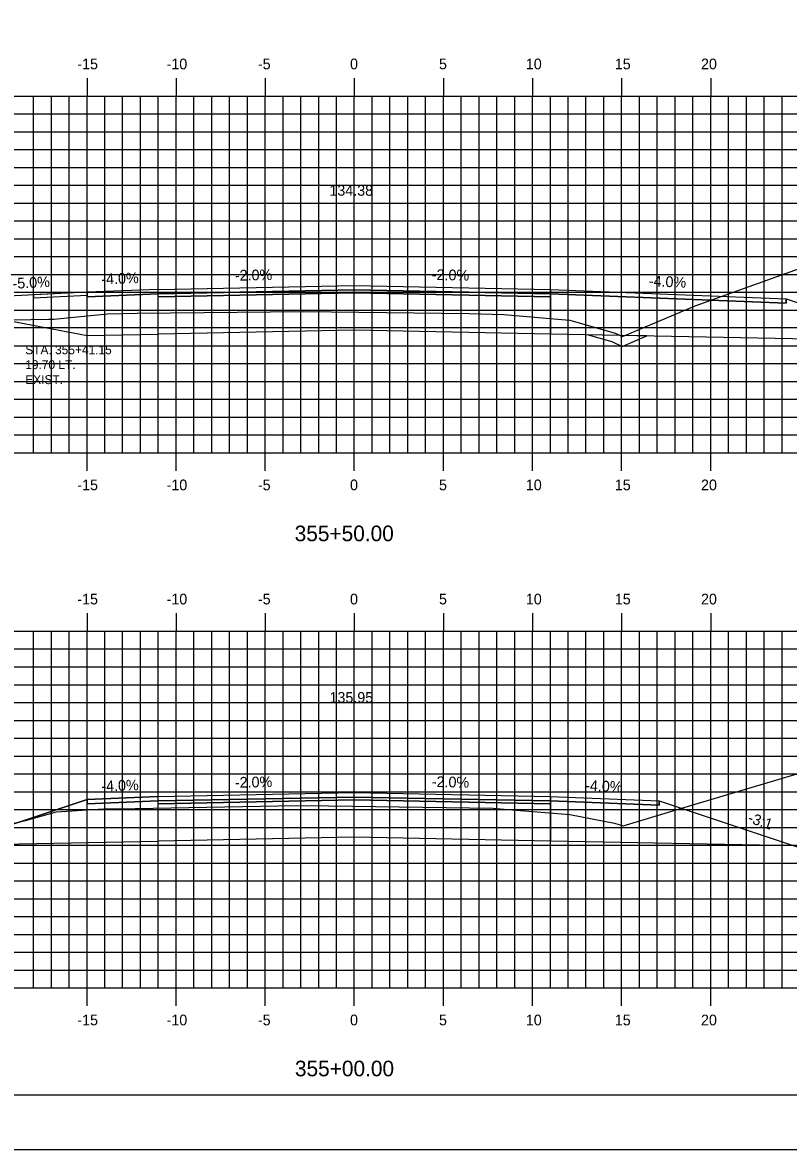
# Model space of a CAD drawing. Extents: x 1145416 to 1145586, y 608981 to 609091.
# Drawn here: x 1145480.3 to 1145523.3, y 608981.3 to 609044.5 of the extents above; entities that cross this region are included whole.
import ezdxf

# ---------------------------------------------------------------- set-up
doc = ezdxf.new("R2010")
doc.units = 0
for name, color, linetype in [('ANNOTATION', 7, 'Continuous'), ('BORDER', 7, 'Continuous'), ('D_Roadway_Centerline', 7, 'Continuous'), ('D_Roadway_Centerline_Text', 7, 'Continuous'), ('D_Roadway_Edge_Shoulder', 7, 'Continuous'), ('D_Roadway_Edge_TW', 7, 'Continuous'), ('D_Roadway_Pavement', 7, 'Continuous'), ('D_Roadway_SubGrade', 7, 'Continuous'), ('D_Text_Monospaced', 7, 'Continuous'), ('H_V ANNOTATION', 7, 'Continuous'), ('MAJOR', 7, 'Continuous'), ('MINOR', 7, 'Continuous'), ('PLOT BOUNDARY', 7, 'Continuous'), ('S_Roadway_Centerline', 7, 'Continuous'), ('SHADING', 7, 'Continuous')]:
    doc.layers.add(name, color=color, linetype=linetype)

msp = doc.modelspace()

# ---------------------------------------------------------------- linework, layer by layer
msp.add_lwpolyline([(1145459.897, 609002.864), (1145461.147, 609002.721), (1145462.397, 609002.44), (1145463.647, 609002.022), (1145464.897, 609001.465), (1145473.164, 608997.332), (1145476.164, 608998.332), (1145483.888, 609000.906), (1145483.889, 609000.906), (1145487.889, 609001.066), (1145498.889, 609001.286), (1145509.889, 609001.066), (1145515.987, 609000.823), (1145523.577, 608998.293), (1145526.577, 608997.293), (1145535.165, 609001.587), (1145536.415, 609002.14), (1145537.665, 609002.548), (1145538.915, 609002.812), (1145540.165, 609002.931)])
at = {"layer": 'BORDER'}
msp.add_lwpolyline([(1145423.889, 608984.335), (1145583.889, 608984.335), (1145583.889, 609089.335), (1145423.889, 609089.335)], close=True, dxfattribs=at)
at = {"layer": 'D_Roadway_Edge_Shoulder'}
for points in [[(1145483.889, 609029.335), (1145480.889, 609029.188), (1145480.889, 609029.021), (1145483.889, 609029.171)], [(1145487.889, 609029.495), (1145483.889, 609029.335), (1145483.889, 609029.085), (1145487.889, 609029.245)], [(1145509.889, 609029.495), (1145523.13, 609028.966), (1145523.13, 609028.716), (1145509.889, 609029.245)], [(1145487.889, 609001.066), (1145483.889, 609000.906), (1145483.889, 609000.656), (1145487.889, 609000.816)], [(1145509.889, 609001.066), (1145515.987, 609000.823), (1145515.987, 609000.573), (1145509.889, 609000.816)]]:
    msp.add_lwpolyline(points, close=True, dxfattribs=at)
at = {"layer": 'D_Roadway_Edge_TW'}
for points in [[(1145487.889, 609029.245), (1145487.889, 609029.495), (1145498.889, 609029.715), (1145509.889, 609029.495), (1145509.889, 609029.245), (1145498.889, 609029.465)], [(1145487.889, 609000.816), (1145487.889, 609001.066), (1145498.889, 609001.286), (1145509.889, 609001.066), (1145509.889, 609000.816), (1145498.889, 609001.036)]]:
    msp.add_lwpolyline(points, close=True, dxfattribs=at)
at = {"layer": 'D_Roadway_Pavement'}
for points in [[(1145487.889, 609029.079), (1145487.889, 609029.245), (1145498.889, 609029.465), (1145509.889, 609029.245), (1145509.889, 609029.079), (1145498.889, 609029.299)], [(1145487.889, 609000.65), (1145487.889, 609000.816), (1145498.889, 609001.036), (1145509.889, 609000.816), (1145509.889, 609000.65), (1145498.889, 609000.87)]]:
    msp.add_lwpolyline(points, close=True, dxfattribs=at)
at = {"layer": 'D_Roadway_SubGrade'}
for points in [[(1145477.987, 609028.04), (1145483.889, 609026.915), (1145487.889, 609026.995), (1145487.889, 609029.079), (1145487.889, 609029.245), (1145483.889, 609029.085), (1145483.889, 609029.335), (1145477.987, 609029.04)], [(1145487.889, 609026.995), (1145487.889, 609029.079), (1145498.889, 609029.299), (1145509.889, 609029.079), (1145509.889, 609026.995), (1145498.889, 609027.215)], [(1145509.889, 609029.079), (1145509.889, 609029.245), (1145523.13, 609028.716), (1145523.13, 609028.966), (1145523.13, 609028.966), (1145530.264, 609026.588), (1145509.889, 609026.995)], [(1145487.889, 609000.65), (1145487.889, 609000.816), (1145483.889, 609000.656), (1145483.889, 609000.906), (1145483.888, 609000.906), (1145476.164, 608998.332), (1145487.889, 608998.566)], [(1145487.889, 608998.566), (1145487.889, 609000.65), (1145498.889, 609000.87), (1145509.889, 609000.65), (1145509.889, 608998.566), (1145498.889, 608998.786)], [(1145509.889, 609000.65), (1145509.889, 609000.816), (1145515.987, 609000.573), (1145515.987, 609000.823), (1145515.987, 609000.823), (1145523.577, 608998.293), (1145509.889, 608998.566)]]:
    msp.add_lwpolyline(points, close=True, dxfattribs=at)
msp.add_lwpolyline([(1145512.02, 609026.953), (1145513.341, 609026.572), (1145513.92, 609026.299), (1145515.303, 609026.887)], dxfattribs=at)
at = {"layer": 'MAJOR'}
for p, q in [((1145483.889, 609041.337), (1145483.889, 609040.335)), ((1145488.889, 609041.337), (1145488.889, 609040.335)), ((1145493.889, 609041.337), (1145493.889, 609040.335)), ((1145498.889, 609041.337), (1145498.889, 609040.335)), ((1145503.889, 609041.337), (1145503.889, 609040.335)), ((1145508.889, 609041.337), (1145508.889, 609040.335)), ((1145513.889, 609041.337), (1145513.889, 609040.335)), ((1145518.889, 609041.337), (1145518.889, 609040.335)), ((1145428.889, 609040.335), (1145568.889, 609040.335)), ((1145428.889, 609040.335), (1145568.889, 609040.335)), ((1145483.889, 609020.335), (1145483.889, 609040.335)), ((1145488.889, 609020.335), (1145488.889, 609040.335)), ((1145493.889, 609020.335), (1145493.889, 609040.335)), ((1145498.889, 609020.335), (1145498.889, 609040.335)), ((1145503.889, 609020.335), (1145503.889, 609040.335)), ((1145508.889, 609020.335), (1145508.889, 609040.335)), ((1145513.889, 609020.335), (1145513.889, 609040.335)), ((1145518.889, 609020.335), (1145518.889, 609040.335)), ((1145428.889, 609035.335), (1145568.889, 609035.335)), ((1145428.889, 609030.335), (1145568.889, 609030.335)), ((1145428.889, 609025.335), (1145568.889, 609025.335)), ((1145428.889, 609020.335), (1145568.889, 609020.335)), ((1145428.889, 609020.335), (1145568.889, 609020.335)), ((1145483.889, 609019.333), (1145483.889, 609020.335)), ((1145488.889, 609019.333), (1145488.889, 609020.335)), ((1145493.889, 609019.333), (1145493.889, 609020.335)), ((1145498.889, 609019.333), (1145498.889, 609020.335)), ((1145503.889, 609019.333), (1145503.889, 609020.335)), ((1145508.889, 609019.333), (1145508.889, 609020.335)), ((1145513.889, 609019.333), (1145513.889, 609020.335)), ((1145518.889, 609019.333), (1145518.889, 609020.335)), ((1145483.889, 609011.337), (1145483.889, 609010.335)), ((1145488.889, 609011.337), (1145488.889, 609010.335)), ((1145493.889, 609011.337), (1145493.889, 609010.335)), ((1145498.889, 609011.337), (1145498.889, 609010.335)), ((1145503.889, 609011.337), (1145503.889, 609010.335)), ((1145508.889, 609011.337), (1145508.889, 609010.335)), ((1145513.889, 609011.337), (1145513.889, 609010.335)), ((1145518.889, 609011.337), (1145518.889, 609010.335)), ((1145428.889, 609010.335), (1145568.889, 609010.335)), ((1145428.889, 609010.335), (1145568.889, 609010.335)), ((1145483.889, 608990.335), (1145483.889, 609010.335)), ((1145488.889, 608990.335), (1145488.889, 609010.335)), ((1145493.889, 608990.335), (1145493.889, 609010.335)), ((1145498.889, 608990.335), (1145498.889, 609010.335)), ((1145503.889, 608990.335), (1145503.889, 609010.335)), ((1145508.889, 608990.335), (1145508.889, 609010.335)), ((1145513.889, 608990.335), (1145513.889, 609010.335)), ((1145518.889, 608990.335), (1145518.889, 609010.335)), ((1145428.889, 609005.335), (1145568.889, 609005.335)), ((1145428.889, 609000.335), (1145568.889, 609000.335)), ((1145428.889, 608995.335), (1145568.889, 608995.335)), ((1145428.889, 608990.335), (1145568.889, 608990.335)), ((1145428.889, 608990.335), (1145568.889, 608990.335)), ((1145483.889, 608989.333), (1145483.889, 608990.335)), ((1145488.889, 608989.333), (1145488.889, 608990.335)), ((1145493.889, 608989.333), (1145493.889, 608990.335)), ((1145498.889, 608989.333), (1145498.889, 608990.335)), ((1145503.889, 608989.333), (1145503.889, 608990.335)), ((1145508.889, 608989.333), (1145508.889, 608990.335)), ((1145513.889, 608989.333), (1145513.889, 608990.335)), ((1145518.889, 608989.333), (1145518.889, 608990.335))]:
    msp.add_line(p, q, dxfattribs=at)
at = {"layer": 'MINOR'}
for p, q in [((1145480.889, 609020.335), (1145480.889, 609040.335)), ((1145481.889, 609020.335), (1145481.889, 609040.335)), ((1145482.889, 609020.335), (1145482.889, 609040.335)), ((1145484.889, 609020.335), (1145484.889, 609040.335)), ((1145485.889, 609020.335), (1145485.889, 609040.335)), ((1145486.889, 609020.335), (1145486.889, 609040.335)), ((1145487.889, 609020.335), (1145487.889, 609040.335)), ((1145489.889, 609020.335), (1145489.889, 609040.335)), ((1145490.889, 609020.335), (1145490.889, 609040.335)), ((1145491.889, 609020.335), (1145491.889, 609040.335)), ((1145492.889, 609020.335), (1145492.889, 609040.335)), ((1145494.889, 609020.335), (1145494.889, 609040.335)), ((1145495.889, 609020.335), (1145495.889, 609040.335)), ((1145496.889, 609020.335), (1145496.889, 609040.335)), ((1145497.889, 609020.335), (1145497.889, 609040.335)), ((1145499.889, 609020.335), (1145499.889, 609040.335)), ((1145500.889, 609020.335), (1145500.889, 609040.335)), ((1145501.889, 609020.335), (1145501.889, 609040.335)), ((1145502.889, 609020.335), (1145502.889, 609040.335)), ((1145504.889, 609020.335), (1145504.889, 609040.335)), ((1145505.889, 609020.335), (1145505.889, 609040.335)), ((1145506.889, 609020.335), (1145506.889, 609040.335)), ((1145507.889, 609020.335), (1145507.889, 609040.335)), ((1145509.889, 609020.335), (1145509.889, 609040.335)), ((1145510.889, 609020.335), (1145510.889, 609040.335)), ((1145511.889, 609020.335), (1145511.889, 609040.335)), ((1145512.889, 609020.335), (1145512.889, 609040.335)), ((1145514.889, 609020.335), (1145514.889, 609040.335)), ((1145515.889, 609020.335), (1145515.889, 609040.335)), ((1145516.889, 609020.335), (1145516.889, 609040.335)), ((1145517.889, 609020.335), (1145517.889, 609040.335)), ((1145519.889, 609020.335), (1145519.889, 609040.335)), ((1145520.889, 609020.335), (1145520.889, 609040.335)), ((1145521.889, 609020.335), (1145521.889, 609040.335)), ((1145522.889, 609020.335), (1145522.889, 609040.335)), ((1145428.889, 609039.335), (1145568.889, 609039.335)), ((1145428.889, 609038.335), (1145568.889, 609038.335)), ((1145428.889, 609037.335), (1145568.889, 609037.335)), ((1145428.889, 609036.335), (1145568.889, 609036.335)), ((1145428.889, 609034.335), (1145568.889, 609034.335)), ((1145428.889, 609033.335), (1145568.889, 609033.335)), ((1145428.889, 609032.335), (1145568.889, 609032.335)), ((1145428.889, 609031.335), (1145568.889, 609031.335)), ((1145428.889, 609029.335), (1145568.889, 609029.335)), ((1145428.889, 609028.335), (1145568.889, 609028.335)), ((1145568.889, 609027.335), (1145428.889, 609027.335)), ((1145428.889, 609026.335), (1145568.889, 609026.335)), ((1145428.889, 609024.335), (1145568.889, 609024.335)), ((1145428.889, 609023.335), (1145568.889, 609023.335)), ((1145428.889, 609022.335), (1145568.889, 609022.335)), ((1145428.889, 609021.335), (1145568.889, 609021.335)), ((1145480.889, 608990.335), (1145480.889, 609010.335)), ((1145481.889, 608990.335), (1145481.889, 609010.335)), ((1145482.889, 608990.335), (1145482.889, 609010.335)), ((1145484.889, 608990.335), (1145484.889, 609010.335)), ((1145485.889, 608990.335), (1145485.889, 609010.335)), ((1145486.889, 608990.335), (1145486.889, 609010.335)), ((1145487.889, 608990.335), (1145487.889, 609010.335)), ((1145489.889, 608990.335), (1145489.889, 609010.335)), ((1145490.889, 608990.335), (1145490.889, 609010.335)), ((1145491.889, 608990.335), (1145491.889, 609010.335)), ((1145492.889, 608990.335), (1145492.889, 609010.335)), ((1145494.889, 608990.335), (1145494.889, 609010.335)), ((1145495.889, 608990.335), (1145495.889, 609010.335)), ((1145496.889, 608990.335), (1145496.889, 609010.335)), ((1145497.889, 608990.335), (1145497.889, 609010.335)), ((1145499.889, 608990.335), (1145499.889, 609010.335)), ((1145500.889, 608990.335), (1145500.889, 609010.335)), ((1145501.889, 608990.335), (1145501.889, 609010.335)), ((1145502.889, 608990.335), (1145502.889, 609010.335)), ((1145504.889, 608990.335), (1145504.889, 609010.335)), ((1145505.889, 608990.335), (1145505.889, 609010.335)), ((1145506.889, 608990.335), (1145506.889, 609010.335)), ((1145507.889, 608990.335), (1145507.889, 609010.335)), ((1145509.889, 608990.335), (1145509.889, 609010.335)), ((1145510.889, 608990.335), (1145510.889, 609010.335)), ((1145511.889, 608990.335), (1145511.889, 609010.335)), ((1145512.889, 608990.335), (1145512.889, 609010.335)), ((1145514.889, 608990.335), (1145514.889, 609010.335)), ((1145515.889, 608990.335), (1145515.889, 609010.335)), ((1145516.889, 608990.335), (1145516.889, 609010.335)), ((1145517.889, 608990.335), (1145517.889, 609010.335)), ((1145519.889, 608990.335), (1145519.889, 609010.335)), ((1145520.889, 608990.335), (1145520.889, 609010.335)), ((1145521.889, 608990.335), (1145521.889, 609010.335)), ((1145522.889, 608990.335), (1145522.889, 609010.335)), ((1145428.889, 609009.335), (1145568.889, 609009.335)), ((1145428.889, 609008.335), (1145568.889, 609008.335)), ((1145428.889, 609007.335), (1145568.889, 609007.335)), ((1145428.889, 609006.335), (1145568.889, 609006.335)), ((1145428.889, 609004.335), (1145568.889, 609004.335)), ((1145428.889, 609003.335), (1145568.889, 609003.335)), ((1145428.889, 609002.335), (1145568.889, 609002.335)), ((1145428.889, 609001.335), (1145568.889, 609001.335)), ((1145428.889, 608999.335), (1145568.889, 608999.335)), ((1145428.889, 608998.335), (1145568.889, 608998.335)), ((1145428.889, 608997.335), (1145568.889, 608997.335)), ((1145428.889, 608996.335), (1145568.889, 608996.335)), ((1145428.889, 608994.335), (1145568.889, 608994.335)), ((1145428.889, 608993.335), (1145568.889, 608993.335)), ((1145428.889, 608992.335), (1145568.889, 608992.335)), ((1145428.889, 608991.335), (1145568.889, 608991.335))]:
    msp.add_line(p, q, dxfattribs=at)
at = {"layer": 'PLOT BOUNDARY'}
msp.add_lwpolyline([(1145415.795, 608981.276), (1145585.795, 608981.276), (1145585.795, 609091.276), (1145415.795, 609091.276)], close=True, dxfattribs=at)
at = {"layer": 'S_Roadway_Centerline'}
for points in [[(1145438.43, 609028.386), (1145453.335, 609028.272), (1145460.467, 609027.94), (1145466.247, 609027.089), (1145466.648, 609027.096), (1145466.887, 609027.122), (1145469.265, 609027.152), (1145471.189, 609027.579), (1145474.917, 609027.67), (1145478.695, 609027.772), (1145481.741, 609027.82), (1145482.031, 609027.818), (1145485.039, 609028.121), (1145486.704, 609028.157), (1145496.051, 609028.259), (1145505.332, 609028.136), (1145507.282, 609028.095), (1145510.304, 609027.832), (1145510.979, 609027.773), (1145513.518, 609027.042), (1145513.931, 609026.847), (1145518.014, 609028.583), (1145525.127, 609031.11)], [(1145440.356, 609003.793), (1145453.175, 609003.264), (1145465.44, 609002.534), (1145473.538, 609000.489), (1145477.984, 608999.152), (1145480.44, 608999.716), (1145482.168, 609000.197), (1145484.192, 609000.33), (1145484.829, 609000.367), (1145486.595, 609000.386), (1145495.634, 609000.566), (1145497.444, 609000.542), (1145506.677, 609000.41), (1145507.295, 609000.357), (1145510.974, 609000.051), (1145513.492, 608999.566), (1145513.977, 608999.427), (1145517.137, 609000.366), (1145523.601, 609002.296), (1145524.098, 609002.327), (1145545.847, 609003.145)]]:
    msp.add_lwpolyline(points, dxfattribs=at)
at = {"layer": 'SHADING'}
for p, q in [((1145513.782, 609026.917), (1145512.02, 609026.953)), ((1145515.303, 609026.887), (1145514.082, 609026.911))]:
    msp.add_line(p, q, dxfattribs=at)
for points in [[(1145512.02, 609026.953), (1145513.341, 609026.572), (1145513.92, 609026.299), (1145515.303, 609026.887)], [(1145514.082, 609026.911), (1145513.931, 609026.847), (1145513.782, 609026.917)]]:
    msp.add_lwpolyline(points, dxfattribs=at)

# ---------------------------------------------------------------- texts
at = {"layer": 'ANNOTATION'}
for s, rotation, p in [('-4.0%', 2.29061, (1145484.704, 609029.769)), ('-2.0%', 1.14576, (1145492.192, 609029.982)), ('-2.0%', 358.85424, (1145503.232, 609030.029)), ('-5.0%', 2.86241, (1145479.723, 609029.528)), ('-4.0%', 357.70939, (1145515.405, 609029.675)), ('-4.0%', 2.29061, (1145484.704, 609001.34)), ('-2.0%', 1.14576, (1145492.192, 609001.553)), ('-2.0%', 358.85424, (1145503.232, 609001.6)), ('-4.0%', 357.70939, (1145511.834, 609001.389)), ('-3:1', 341.56522, (1145520.931, 608999.629))]:
    msp.add_text(s, height=0.6, rotation=rotation, dxfattribs=at).set_placement(p)
at = {"layer": 'D_Roadway_Centerline'}
for s, p in [('C', (1145498.883, 609029.715)), ('L', (1145498.889, 609029.708)), ('C', (1145498.883, 609001.286)), ('L', (1145498.889, 609001.279))]:
    msp.add_text(s, height=0.0146, dxfattribs=at).set_placement(p)
at = {"layer": 'D_Roadway_Centerline_Text'}
for s, p in [('134.38', (1145497.489, 609034.747)), ('135.95', (1145497.495, 609006.318))]:
    msp.add_text(s, height=0.6, dxfattribs=at).set_placement(p)
at = {"layer": 'D_Text_Monospaced'}
for s, height, p in [('STA. 355+41.15', 0.49998, (1145480.424, 609025.86)), ('19.70 LT.', 0.5, (1145480.424, 609025.026)), ('EXIST. ', 0.5, (1145480.424, 609024.186))]:
    msp.add_text(s, height=height, dxfattribs=at).set_placement(p)
at = {"layer": 'H_V ANNOTATION'}
for s, height, p in [('-15', 0.6, (1145483.345, 609041.835)), ('-10', 0.6, (1145488.353, 609041.835)), ('-5', 0.6, (1145493.479, 609041.835)), ('0', 0.6, (1145498.648, 609041.835)), ('5', 0.6, (1145503.64, 609041.835)), ('10', 0.6, (1145508.514, 609041.835)), ('15', 0.6, (1145513.506, 609041.835)), ('20', 0.6, (1145518.343, 609041.835)), ('-15', 0.6, (1145483.345, 609018.235)), ('-10', 0.6, (1145488.353, 609018.235)), ('-5', 0.6, (1145493.479, 609018.235)), ('0', 0.6, (1145498.648, 609018.235)), ('5', 0.6, (1145503.64, 609018.235)), ('10', 0.6, (1145508.514, 609018.235)), ('15', 0.6, (1145513.506, 609018.235)), ('20', 0.6, (1145518.343, 609018.235)), ('355+50.00', 0.875, (1145495.541, 609015.378)), ('-15', 0.6, (1145483.345, 609011.835)), ('-10', 0.6, (1145488.353, 609011.835)), ('-5', 0.6, (1145493.479, 609011.835)), ('0', 0.6, (1145498.648, 609011.835)), ('5', 0.6, (1145503.64, 609011.835)), ('10', 0.6, (1145508.514, 609011.835)), ('15', 0.6, (1145513.506, 609011.835)), ('20', 0.6, (1145518.343, 609011.835)), ('-15', 0.6, (1145483.345, 608988.235)), ('-10', 0.6, (1145488.353, 608988.235)), ('-5', 0.6, (1145493.479, 608988.235)), ('0', 0.6, (1145498.648, 608988.235)), ('5', 0.6, (1145503.64, 608988.235)), ('10', 0.6, (1145508.514, 608988.235)), ('15', 0.6, (1145513.506, 608988.235)), ('20', 0.6, (1145518.343, 608988.235)), ('355+00.00', 0.875, (1145495.556, 608985.378))]:
    msp.add_text(s, height=height, dxfattribs=at).set_placement(p)
at = {"layer": 'S_Roadway_Centerline'}
for s, p in [('L', (1145496.043, 609028.252)), ('C', (1145496.046, 609028.259)), ('C', (1145495.629, 609000.566)), ('L', (1145495.626, 609000.559))]:
    msp.add_text(s, height=0.0146, dxfattribs=at).set_placement(p)

doc.saveas('drawing.dxf')
